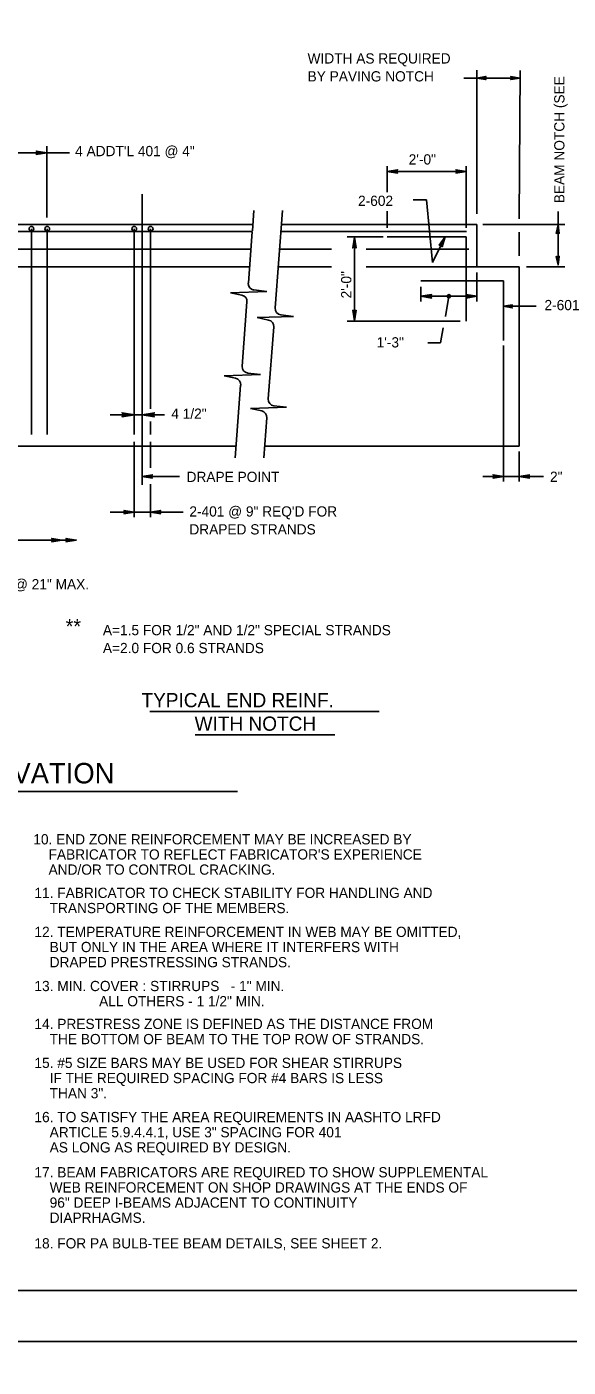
# Model space of a CAD drawing. Extents: x 637933 to 640019, y 298854 to 300042.
# Drawn here: x 638230.3 to 638388.8, y 299440.6 to 299833.4 of the extents above; entities that cross this region are included whole.
import ezdxf

# ---------------------------------------------------------------- set-up
doc = ezdxf.new("R2010")
doc.units = 0
doc.layers.add('1', color=7, linetype='Continuous')
doc.layers.add('PLT-BNDY', color=7, linetype='Continuous')

msp = doc.modelspace()

# ---------------------------------------------------------------- linework, layer by layer
at = {"layer": '1'}
for p, q in [((638362.11, 299778.64), (638362.11, 299820.7)), ((638374.48, 299777.18), (638374.74, 299820.63)), ((638362.11, 299818.33), (638358.32, 299818.33)), ((638374.65, 299818.33), (638362.11, 299818.33)), ((638236.18, 299798.42), (638236.18, 299777.53)), ((638222.43, 299796.49), (638242.78, 299796.49)), ((638335.86, 299784.92), (638335.86, 299792.54)), ((638358.98, 299791.04), (638335.86, 299791.04)), ((638358.98, 299774.5), (638358.98, 299792.54)), ((638264.08, 299784.35), (638264.08, 299699.21)), ((638347.38, 299782.68), (638343.42, 299782.68)), ((638349.11, 299764.35), (638347.38, 299782.68)), ((638296.77, 299779.6), (638296.33, 299773.66)), ((638305.16, 299779.6), (638303, 299751.02)), ((638335.86, 299774.5), (638335.86, 299779.36)), ((638385.86, 299775.36), (638385.86, 299779.32)), ((638296.43, 299775.48), (638070.19, 299775.48)), ((638102.44, 299773.38), (638296.31, 299773.38)), ((638231.63, 299774.23), (638231.63, 299713.89)), ((638231.63, 299774.23), (638231.63, 299774.23)), ((638231.63, 299774.23), (638231.63, 299774.23)), ((638231.63, 299774.23), (638231.63, 299774.23)), ((638231.63, 299774.23), (638231.63, 299774.23)), ((638236.26, 299774.23), (638236.26, 299713.89)), ((638236.26, 299774.23), (638236.26, 299774.23)), ((638236.26, 299774.23), (638236.26, 299774.23)), ((638236.26, 299774.23), (638236.26, 299774.23)), ((638236.26, 299774.23), (638236.26, 299774.23)), ((638261.75, 299774.23), (638261.75, 299713.89)), ((638261.75, 299774.23), (638261.75, 299774.23)), ((638261.75, 299774.23), (638261.75, 299774.23)), ((638261.75, 299774.23), (638261.75, 299774.23)), ((638261.75, 299774.23), (638261.75, 299774.23)), ((638266.54, 299774.23), (638266.54, 299721.49)), ((638266.54, 299774.23), (638266.54, 299774.23)), ((638266.54, 299774.23), (638266.54, 299774.23)), ((638266.54, 299774.23), (638266.54, 299774.23)), ((638266.54, 299774.23), (638266.54, 299774.23)), ((638296.3, 299773.38), (638295.16, 299758.28)), ((638304.69, 299773.38), (638359.07, 299773.38)), ((638362.11, 299775.48), (638304.98, 299775.48)), ((638362.11, 299763.11), (638362.11, 299775.48)), ((638387.86, 299775.48), (638363.86, 299775.48)), ((638374.48, 299766.3), (638374.48, 299773.22)), ((638385.86, 299763.61), (638385.86, 299775.36)), ((638334.61, 299771.86), (638324.14, 299771.86)), ((638326.23, 299747.24), (638326.23, 299771.74)), ((638358.98, 299771.86), (638335.86, 299771.86)), ((638352.83, 299771.86), (638349.11, 299764.35)), ((638358.98, 299747.11), (638358.98, 299771.86)), ((638295.92, 299768.23), (638071.79, 299768.23)), ((638319.53, 299768.23), (638304.3, 299768.23)), ((638359.72, 299768.23), (638329.67, 299768.23)), ((638295.4, 299763.11), (638070.19, 299763.11)), ((638319.53, 299763.11), (638303.96, 299763.11)), ((638374.48, 299763.11), (638329.67, 299763.11)), ((638374.48, 299763.11), (638362.11, 299763.11)), ((638362.11, 299752.89), (638362.11, 299761.37)), ((638374.48, 299710.48), (638374.48, 299763.11)), ((638387.86, 299763.11), (638376.61, 299763.11)), ((638369.86, 299758.98), (638345.7, 299758.98)), ((638369.86, 299741.48), (638369.86, 299758.98)), ((638300.54, 299755.83), (638289.93, 299755.48)), ((638289.93, 299755.48), (638293.28, 299754.75)), ((638296.81, 299756.28), (638300.54, 299755.83)), ((638345.7, 299752.89), (638345.7, 299757.24)), ((638345.7, 299754.43), (638362.11, 299754.43)), ((638352.86, 299748.55), (638353.91, 299754.43)), ((638294.75, 299752.78), (638293.33, 299733.94)), ((638379.49, 299751.55), (638369.86, 299751.55)), ((638308.37, 299748.56), (638297.76, 299748.22)), ((638297.76, 299748.22), (638301.11, 299747.48)), ((638302.58, 299745.51), (638300.99, 299724.36)), ((638304.64, 299749.02), (638308.37, 299748.56)), ((638357.23, 299747.11), (638324.11, 299747.11)), ((638351.47, 299740.75), (638352.27, 299745.24)), ((638347.72, 299740.75), (638351.47, 299740.75)), ((638369.86, 299739.98), (638369.86, 299700.13)), ((638298.7, 299731.48), (638288.09, 299731.14)), ((638288.09, 299731.14), (638291.44, 299730.41)), ((638294.97, 299731.94), (638298.7, 299731.48)), ((638292.91, 299728.43), (638291.3, 299707.07)), ((638302.63, 299722.36), (638306.36, 299721.91)), ((638374.48, 299710.48), (638374.48, 299725.51)), ((638270.6, 299719.72), (638254.69, 299719.72)), ((638306.36, 299721.91), (638295.75, 299721.56)), ((638295.75, 299721.56), (638299.1, 299720.83)), ((638300.57, 299718.86), (638299.68, 299707.07)), ((638266.54, 299717.78), (638266.54, 299713.89)), ((638291.56, 299710.48), (638070.19, 299710.48)), ((638261.71, 299689.71), (638261.71, 299711.76)), ((638266.51, 299711.76), (638266.51, 299704.13)), ((638374.48, 299710.48), (638299.94, 299710.48)), ((638374.48, 299708.98), (638374.48, 299700.13)), ((638264.08, 299701.65), (638274.97, 299701.65)), ((638266.51, 299699.34), (638266.51, 299689.71)), ((638381.61, 299701.63), (638363.86, 299701.63)), ((638254.69, 299691.21), (638276.1, 299691.21)), ((638261.71, 299690.17), (638261.71, 299691.21)), ((638171.07, 299682.98), (638244.74, 299682.98)), ((638333.5, 299632.76), (638266.31, 299632.76)), ((638320.48, 299625.88), (638279.54, 299625.88)), ((638291.96, 299609.31), (638138.54, 299609.31)), ((638809.94, 299463.12), (638023.93, 299463.12))]:
    msp.add_line(p, q, dxfattribs=at)
for points in [[(638364.49, 299818.08), (638364.36, 299818.21), (638362.11, 299818.33), (638364.49, 299818.08), (638364.61, 299817.96), (638362.11, 299818.33), (638364.36, 299818.46), (638364.49, 299818.71), (638362.11, 299818.33), (638364.61, 299818.83), (638364.49, 299818.71)], [(638364.65, 299818.08), (638364.53, 299818.21), (638362.28, 299818.33), (638364.65, 299818.08), (638364.78, 299817.96), (638362.28, 299818.33), (638364.53, 299818.46), (638364.65, 299818.71), (638362.28, 299818.33), (638364.78, 299818.83), (638364.65, 299818.71)], [(638372.15, 299818.71), (638372.28, 299818.46), (638374.65, 299818.33), (638372.15, 299818.71), (638372.03, 299818.83), (638374.65, 299818.33), (638372.28, 299818.21), (638372.15, 299818.08), (638374.65, 299818.33), (638372.03, 299817.96), (638372.15, 299818.08)], [(638233.18, 299796.87), (638233.3, 299796.74), (638236.18, 299796.49), (638233.18, 299796.87), (638233.05, 299796.99), (638236.18, 299796.49), (638233.3, 299796.37), (638233.18, 299796.24), (638236.18, 299796.49), (638233.05, 299795.99), (638233.18, 299796.24)], [(638338.71, 299790.68), (638338.61, 299790.88), (638335.86, 299791.04), (638338.71, 299790.68), (638338.86, 299790.55), (638335.86, 299791.04), (638338.61, 299791.17), (638338.71, 299791.38), (638335.86, 299791.04), (638338.86, 299791.51), (638338.71, 299791.38)], [(638356.13, 299791.39), (638356.24, 299791.19), (638358.98, 299791.04), (638356.13, 299791.39), (638355.98, 299791.52), (638358.98, 299791.04), (638356.24, 299790.9), (638356.14, 299790.7), (638358.98, 299791.04), (638355.98, 299790.56), (638356.14, 299790.7)], [(638385.48, 299772.98), (638385.73, 299772.98), (638385.86, 299775.36), (638385.48, 299772.98), (638385.36, 299772.86), (638385.86, 299775.36), (638385.98, 299772.98), (638386.11, 299772.98), (638385.86, 299775.36), (638386.23, 299772.86), (638386.11, 299772.98)], [(638325.86, 299768.74), (638325.98, 299768.86), (638326.23, 299771.74), (638325.86, 299768.74), (638325.73, 299768.61), (638326.23, 299771.74), (638326.36, 299768.86), (638326.61, 299768.74), (638326.23, 299771.74), (638326.73, 299768.61), (638326.61, 299768.74)], [(638351.24, 299769.46), (638351.48, 299769.47), (638352.83, 299771.86), (638351.24, 299769.46), (638351.07, 299769.39), (638352.83, 299771.86), (638351.73, 299769.34), (638351.87, 299769.16), (638352.83, 299771.86), (638351.93, 299768.96), (638351.87, 299769.16)], [(638386.11, 299765.98), (638385.98, 299765.86), (638385.86, 299763.61), (638386.11, 299765.98), (638386.23, 299766.11), (638385.86, 299763.61), (638385.73, 299765.86), (638385.48, 299765.98), (638385.86, 299763.61), (638385.36, 299766.11), (638385.48, 299765.98)], [(638348.7, 299754.06), (638348.58, 299754.31), (638345.7, 299754.43), (638348.7, 299754.06), (638348.83, 299753.93), (638345.7, 299754.43), (638348.58, 299754.56), (638348.7, 299754.81), (638345.7, 299754.43), (638348.83, 299754.93), (638348.7, 299754.81)], [(638359.11, 299754.81), (638359.23, 299754.56), (638362.11, 299754.43), (638359.11, 299754.81), (638358.98, 299754.93), (638362.11, 299754.43), (638359.23, 299754.31), (638359.11, 299754.06), (638362.11, 299754.43), (638358.98, 299753.93), (638359.11, 299754.06)], [(638326.61, 299750.24), (638326.36, 299750.11), (638326.23, 299747.24), (638326.61, 299750.24), (638326.73, 299750.36), (638326.23, 299747.24), (638326.11, 299750.11), (638325.86, 299750.24), (638326.23, 299747.24), (638325.73, 299750.36), (638325.86, 299750.24)], [(638372.36, 299751.18), (638372.23, 299751.43), (638369.86, 299751.55), (638372.36, 299751.18), (638372.48, 299751.05), (638369.86, 299751.55), (638372.23, 299751.68), (638372.36, 299751.8), (638369.86, 299751.55), (638372.48, 299751.93), (638372.36, 299751.8)], [(638258.34, 299720.14), (638258.47, 299719.9), (638261.77, 299719.71), (638258.34, 299720.14), (638258.17, 299720.29), (638261.77, 299719.71), (638258.47, 299719.55), (638258.35, 299719.31), (638261.77, 299719.71), (638258.17, 299719.14), (638258.35, 299719.31)], [(638267.5, 299719.3), (638267.37, 299719.55), (638264.07, 299719.73), (638267.5, 299719.3), (638267.67, 299719.15), (638264.07, 299719.73), (638267.37, 299719.89), (638267.49, 299720.14), (638264.07, 299719.73), (638267.67, 299720.3), (638267.49, 299720.14)], [(638266.94, 299701.29), (638266.83, 299701.5), (638264.08, 299701.65), (638266.94, 299701.29), (638267.08, 299701.17), (638264.08, 299701.65), (638266.83, 299701.79), (638266.93, 299701.99), (638264.08, 299701.65), (638267.08, 299702.13), (638266.93, 299701.99)], [(638367.01, 299701.99), (638367.11, 299701.79), (638369.86, 299701.63), (638367.01, 299701.99), (638366.86, 299702.12), (638369.86, 299701.63), (638367.11, 299701.5), (638367.01, 299701.29), (638369.86, 299701.63), (638366.86, 299701.16), (638367.01, 299701.29)], [(638377.34, 299701.28), (638377.23, 299701.48), (638374.48, 299701.63), (638377.34, 299701.28), (638377.48, 299701.15), (638374.48, 299701.63), (638377.23, 299701.77), (638377.33, 299701.97), (638374.48, 299701.63), (638377.48, 299702.11), (638377.33, 299701.97)], [(638258.86, 299691.57), (638258.96, 299691.36), (638261.71, 299691.21), (638258.86, 299691.57), (638258.71, 299691.69), (638261.71, 299691.21), (638258.96, 299691.07), (638258.86, 299690.87), (638261.71, 299691.21), (638258.71, 299690.73), (638258.86, 299690.87)], [(638269.36, 299690.85), (638269.25, 299691.05), (638266.51, 299691.21), (638269.36, 299690.85), (638269.51, 299690.72), (638266.51, 299691.21), (638269.25, 299691.34), (638269.35, 299691.55), (638266.51, 299691.21), (638269.51, 299691.68), (638269.35, 299691.55)], [(638237.72, 299683.34), (638237.83, 299683.13), (638240.58, 299682.98), (638237.72, 299683.34), (638237.58, 299683.47), (638240.58, 299682.98), (638237.83, 299682.85), (638237.73, 299682.64), (638240.58, 299682.98), (638237.58, 299682.5), (638237.73, 299682.64)], [(638241.89, 299683.34), (638242, 299683.13), (638244.74, 299682.98), (638241.89, 299683.34), (638241.74, 299683.47), (638244.74, 299682.98), (638242, 299682.85), (638241.9, 299682.64), (638244.74, 299682.98), (638241.74, 299682.5), (638241.9, 299682.64)]]:
    msp.add_lwpolyline(points, dxfattribs=at)
for centre, radius in [((638231.63, 299774.23), 0.7), ((638236.26, 299774.23), 0.7), ((638261.75, 299774.23), 0.7), ((638266.54, 299774.23), 0.7), ((638353.91, 299754.43), 0.495)]:
    msp.add_circle(centre, radius, dxfattribs=at)
for centre, start, end in [((638297.03, 299758.14), 175.7051, 263.0749), ((638292.88, 299752.92), 355.6965, 77.6495), ((638304.87, 299750.88), 175.7051, 263.0749), ((638300.71, 299745.65), 355.6965, 77.6495), ((638295.2, 299733.8), 175.7051, 263.0749), ((638291.04, 299728.58), 355.6965, 77.6495), ((638302.86, 299724.22), 175.7051, 263.0749), ((638298.7, 299719), 355.6965, 77.6495)]:
    msp.add_arc(centre, 1.88, start, end, dxfattribs=at)
at = {"layer": 'PLT-BNDY'}
for points in [[(637983.93, 300042.12), (638824.93, 300042.12), (638824.93, 299448.12), (637983.93, 299448.12)], [(637983.93, 299448.12), (638824.93, 299448.12), (638824.93, 298854.12), (637983.93, 298854.12)]]:
    msp.add_lwpolyline(points, close=True, dxfattribs=at)

# ---------------------------------------------------------------- texts
at = {"layer": '1'}
for s, height, p in [('WIDTH AS REQUIRED', 3, (638312.51, 299822.64)), ('BY PAVING NOTCH', 3, (638312.51, 299817.39)), ('4 ADDT\'L 401 @ 4"', 3, (638244.43, 299795.49)), ('2\'-0"', 3, (638342.12, 299793.05)), ('2-602', 3, (638327.29, 299780.92)), ('2-601', 3, (638381.9, 299750.36)), ('1\'-3"', 3, (638332.74, 299739.44)), ('4 1/2"', 3, (638272.59, 299718.54)), ('DRAPE POINT', 3, (638277.07, 299700.02)), ('2"', 3, (638383.52, 299700.06)), ('2-401 @ 9" REQ\'D FOR', 3, (638277.89, 299689.89)), ('DRAPED STRANDS', 3, (638277.89, 299684.64)), ('404 @ 21" MAX.', 3, (638218.71, 299668.57)), ('**', 4.32, (638241.67, 299655.55)), ('A=1.5 FOR 1/2" AND 1/2" SPECIAL STRANDS', 3, (638252.56, 299655.11)), ('A=2.0 FOR 0.6 STRANDS', 3, (638252.56, 299649.86)), ('TYPICAL END REINF.', 4.1665, (638263.87, 299634.01)), ('WITH NOTCH', 4.167, (638279.42, 299627.13)), ('AASHTO I-BEAM - ELEVATION', 6, (638140.91, 299611.69)), ('10. END ZONE REINFORCEMENT MAY BE INCREASED BY', 3, (638232.19, 299593.82)), ("    FABRICATOR TO REFLECT FABRICATOR'S EXPERIENCE", 3, (638232.19, 299589.38)), ('    AND/OR TO CONTROL CRACKING.', 3, (638232.19, 299584.94)), ('11. FABRICATOR TO CHECK STABILITY FOR HANDLING AND', 3, (638232.51, 299578.12)), ('    TRANSPORTING OF THE MEMBERS.', 3, (638232.51, 299573.67)), ('12. TEMPERATURE REINFORCEMENT IN WEB MAY BE OMITTED,', 3, (638232.51, 299566.69)), ('    BUT ONLY IN THE AREA WHERE IT INTERFERS WITH', 3, (638232.51, 299562.25)), ('    DRAPED PRESTRESSING STRANDS.', 3, (638232.51, 299557.81)), ('13. MIN. COVER : STIRRUPS   - 1" MIN.', 3, (638232.51, 299550.82)), ('                 ALL OTHERS - 1 1/2" MIN.', 3, (638232.51, 299546.38)), ('14. PRESTRESS ZONE IS DEFINED AS THE DISTANCE FROM ', 3, (638232.51, 299539.72)), ('    THE BOTTOM OF BEAM TO THE TOP ROW OF STRANDS.', 3, (638232.51, 299535.27)), ('15. #5 SIZE BARS MAY BE USED FOR SHEAR STIRRUPS ', 3, (638232.51, 299528.29)), ('    IF THE REQUIRED SPACING FOR #4 BARS IS LESS ', 3, (638232.51, 299523.85)), ('    THAN 3".', 3, (638232.51, 299519.41)), ('16. TO SATISFY THE AREA REQUIREMENTS IN AASHTO LRFD', 3, (638232.51, 299512.42)), ('    ARTICLE 5.9.4.4.1, USE 3" SPACING FOR 401', 3, (638232.51, 299507.98)), ('    AS LONG AS REQUIRED BY DESIGN.', 3, (638232.51, 299503.54)), ('17. BEAM FABRICATORS ARE REQUIRED TO SHOW SUPPLEMENTAL', 3, (638232.51, 299496.24)), ('    WEB REINFORCEMENT ON SHOP DRAWINGS AT THE ENDS OF', 3, (638232.51, 299491.8)), ('    96" DEEP I-BEAMS ADJACENT TO CONTINUITY', 3, (638232.51, 299487.36)), ('    DIAPRHAGMS.', 3, (638232.51, 299482.92)), ('18. FOR PA BULB-TEE BEAM DETAILS, SEE SHEET 2.', 3, (638232.51, 299475.42))]:
    msp.add_text(s, height=height, dxfattribs=at).set_placement(p)
for s, p in [('BEAM NOTCH (SEE', (638387.75, 299781.71)), ('2\'-0"', (638325.33, 299753.82))]:
    msp.add_text(s, height=3, rotation=90, dxfattribs=at).set_placement(p)

doc.saveas('drawing.dxf')
